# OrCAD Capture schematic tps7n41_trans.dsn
size A; title: TPS7N41 Transient Model; rev: 1; note: Datasheet: SBVS464
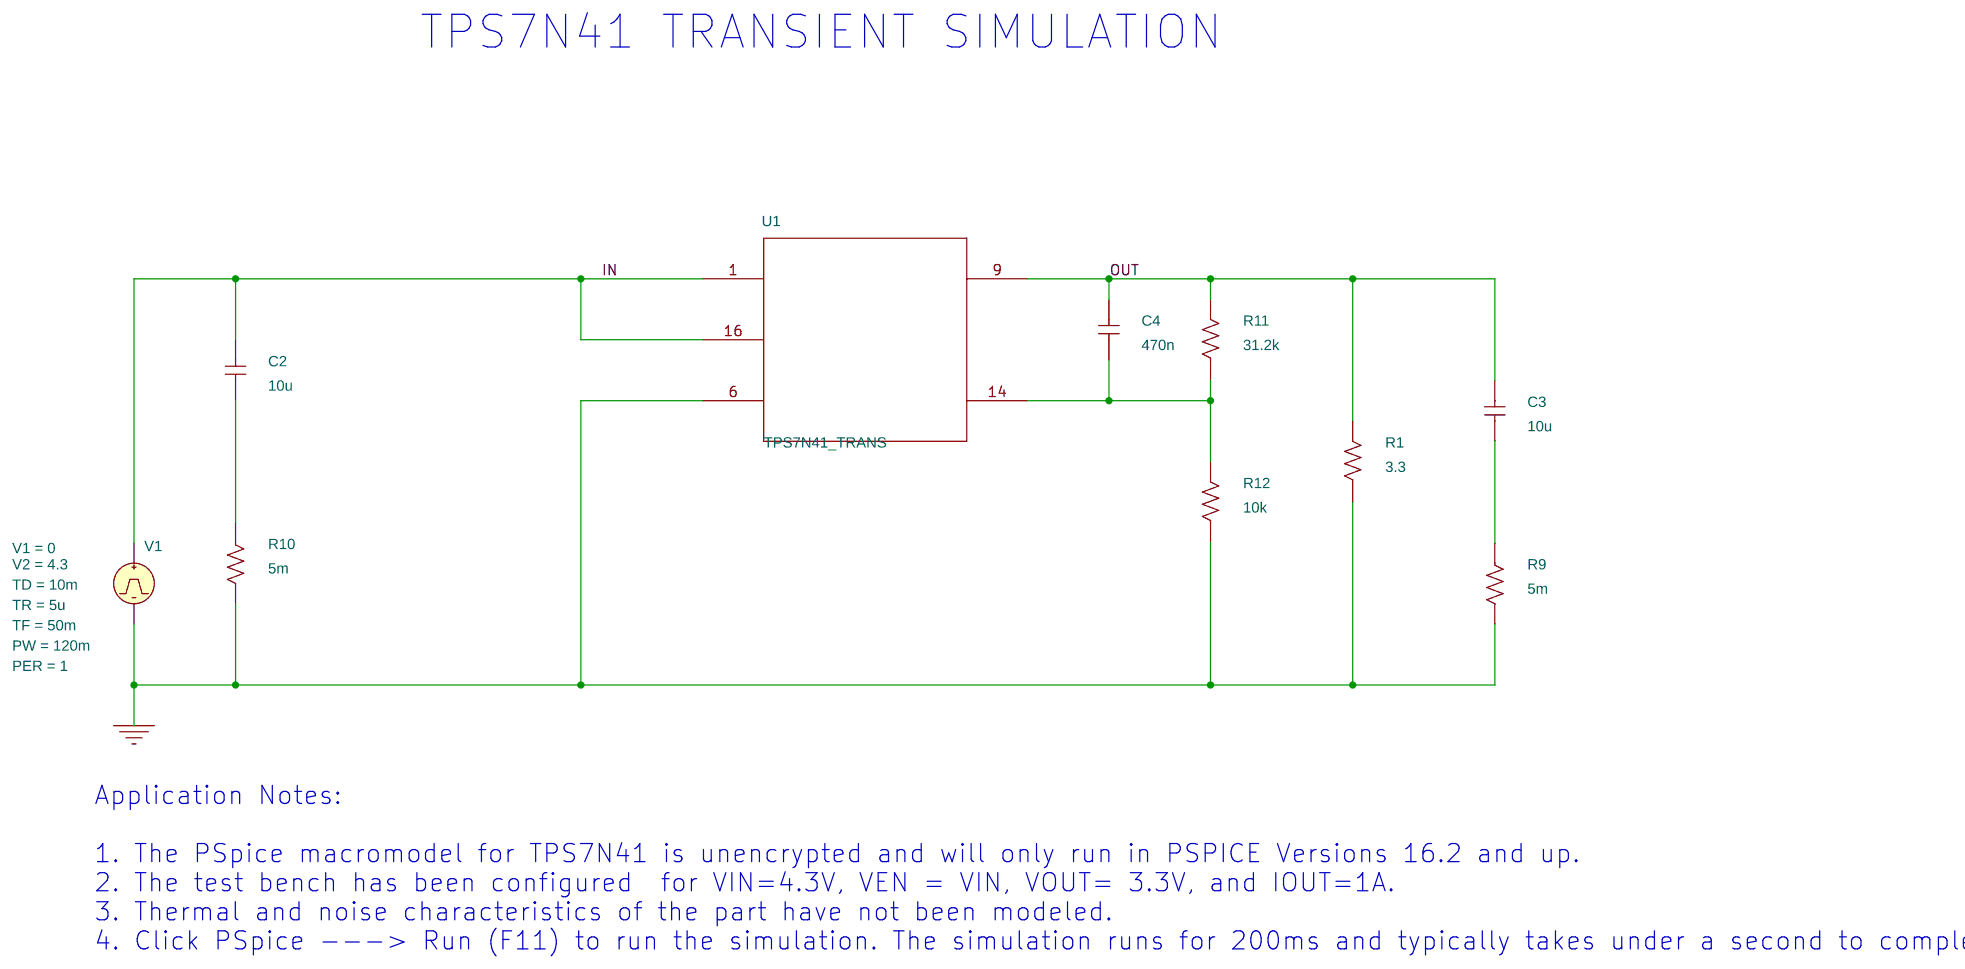
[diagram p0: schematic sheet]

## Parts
C2  10u  [RAD/CK05]
C3  10u  [RAD/CK05]
C4  470n  [RAD/CK05]
R1  3.3  [AX/RC05]
R9  5m  [AX/RC05]
R10  5m  [AX/RC05]
R11  31.2k  [AX/RC05]
R12  10k  [AX/RC05]
U1  TPS7N41_TRANS
V1  VPULSE

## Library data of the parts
C2-C4 = C
R1 R9-R12 = R
U1 = TPS7N41_TRANS
V1 = VPULSE: PER: 1; PW: 120m; TD: 10m; TF: 50m; TR: 5u; V1: 0; V2: 4.3

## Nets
0: R1.1 R9.2 R10.2 R12.1 U1.6(GND) V1.2(-)
IN: C2.2 U1.1(IN) U1.16(EN) V1.1(+)
OUT: C3.2 C4.2 R1.2 R11.2 U1.9(OUT)
N944978: C2.1 R10.1
N945042: C3.1 R9.1
N946006: C4.1 R11.1 R12.2 U1.14(FB)

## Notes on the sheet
- TPS7N41 TRANSIENT SIMULATION
- Application Notes:
  1. The PSpice macromodel for TPS7N41 is unencrypted and will only run in PSPICE Versions 16.2 and up.
  2. The test bench has been configured  for VIN=4.3V, VEN = VIN, VOUT= 3.3V, and IOUT=1A.
  3. Thermal and noise characteristics of the part have not been modeled.
  4. Click PSpice ---> Run (F11) to run the simulation. The simulation runs for 200ms and typically takes under a second to complete.
